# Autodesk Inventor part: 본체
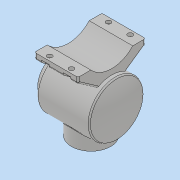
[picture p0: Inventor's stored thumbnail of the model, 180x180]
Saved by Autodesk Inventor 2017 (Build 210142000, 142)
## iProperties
Part Number: 본체
Material: 일반
Document SubType Name: Modeling
Designer: MRC
Density: 1 g/cm^3
Appearance: 기본값
Author: MRC
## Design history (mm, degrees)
sketch "스케치1"
  geometry: L1 (-62, 0)-(58, 0); L2 (41.887, 43)-(-43, 43); L3 (-43, 43)-(-43, 27); L4 (-43, 27)-(-62, 27); L5 (-62, 27)-(-62, 36); L6 (-62, 36)-(-50, 36); L7 (-50, 36)-(-50, 50); L8 (-50, 50)-(46.336, 50); A1 r 106 centre (-55, 0) between (51, 0) and (41.887, 43); A2 r 113 centre (-55, 0) between (58, 0) and (46.336, 50); 1 further point
  constraints: 16 end point, 4 perpendicular, 4 point on circle, 3 horizontal, 3 point on line, 2 centre point, 1 coincident, 1 vertical, 1 vertical alignment
  dimensions: "d6" = 120 distance of L1.end L1.start; "d7" = 62 distance of point (0, 0) L1.start; "d8" = 72 diameter of L6 L1; "d9" = 54 diameter of L4 L1; "d10" = 100 diameter of L8 L1; "d11" = 86 diameter of L2 L1; "d12" = 113 radius of A2; "d14" = 7 radial gap between concentric circles of A2 A1; "d24" = 19 distance of L3.end L4.end; "d25" = 108 distance from line of L7 L1.end
revolve "회전1" sketch "스케치1" stored, may be unused: angle "d15" = 90 deg
node "작업 평면1"
sketch "스케치2"
  geometry: C1 r 36 at (0, 0); 1 further point
  constraints: 1 centre point, 1 coincident
  dimensions: "d17" = 72 diameter of C1
extrude "돌출1" join sketch "스케치2" stored distance "d18" = 10; taper "d19" = 0 deg
node "작업 평면2"
sketch "스케치3"
  geometry: L1 (26.694, 42.278)-(62, 67); L2 (62, 67)-(62, 77); L3 (62, 77)-(38.5, 77); L4 (-26.694, 42.278)-(-62, 67); L5 (-62, 67)-(-62, 77); L6 (-62, 77)-(-38.5, 77); A1 r 50 centre (0, 0) between (26.694, 42.278) and (-26.694, 42.278) reference; A2 r 52.096 centre (0, 112.096) between (-38.5, 77) and (38.5, 77); 1 further point
  constraints: 12 end point, 4 point on circle, 2 equal length, 2 vertical, 1 centre point, 1 collinear, 1 horizontal, 1 perpendicular, 1 vertical alignment
  dimensions: "d26" = 77 distance of L6.end L3.end; "d27" = 77 distance from line of L6 point (0, 0); "d28" = 124 distance between parallel lines of L5 L2; "d29" = 17 distance edge to line of A2 L6; "d30" = 10 distance of L4.end L5.end; "d31" = 55 deg angle of L4 L5; "d32" = 55 deg angle of L1 L2
extrude "돌출2" join sketch "스케치3" distance "d33" = 80; taper "d34" = 0 deg
sketch "스케치4"
  geometry: L1 (0, 0)-(0, 23.5) reference; C1 r 4.5 at (20, 8); 1 further point
  constraints: 1 centre point
  dimensions: "d35" = 54 vertical distance of point (42, 62) C1.centre; "d37" = 9 diameter of C1; "d92" = 20 distance from line of L1 C1.centre
extrude "돌출3" cut sketch "스케치4" distance "d38" = 6; taper "d39" = 0 deg
sketch "스케치5"
  geometry: L1 (7, 0)-(7, -8); L2 (-20, -8)-(60, -8) reference; L3 (-7, 0)-(-7, -8); A1 r 7 centre (0, 0) between (7, 0) and (-7, 0); 1 further point
  constraints: 4 end point, 2 point on circle, 2 point on line, 1 centre point, 1 parallel, 1 perpendicular, 1 tangent
  dimensions: "d46" = 14 diameter of A1
extrude "돌출4" cut sketch "스케치5" stored distance "d47" = 6; taper "d48" = 0 deg
sketch "스케치6"
  geometry: C1 r 27 at (0, 0); 1 further point
  constraints: 1 centre point, 1 coincident
  dimensions: "d52" = 54 diameter of C1
extrude "돌출5" cut sketch "스케치6" stored distance "d53" = 6; taper "d54" = 0 deg
sketch "스케치7"
  geometry: 2 further points
  dimensions: "d55" = 32.5 distance of point (0, 0) point (-32.5, 0)
hole "구멍1" sketch "스케치7" at (-32.5, 0) diameter "d56" = 3.242; stored, may be unused: countersink angle "d60" = 90 deg, drill point angle "d62" = 118 deg; dims "d57" = 8, "d58" = 4, "d59" = 2, "d61" = 10
sketch "스케치8"
  geometry: 2 further points
  dimensions: "d66" = 32.5 distance of point (0, 0) point (-32.5, 0)
hole "구멍2" sketch "스케치8" at (-32.5, 0) diameter "d67" = 3.242; stored, may be unused: countersink angle "d71" = 90 deg, drill point angle "d73" = 118 deg; dims "d68" = 8, "d69" = 4, "d70" = 2, "d72" = 10
sketch "스케치9"
  geometry: 1 further point
fillet "모깎기1" dims "d81" = 3
fillet "모깎기2" dims "d82" = 3
fillet "모깎기3" dims "d83" = 3
fillet "모깎기4" dims "d84" = 3
chamfer "모따기1" distance "d85" = 1; stored, may be unused: second distance "d86" = 2, angle "d87" = 45 deg
node "작업 평면7"
sketch "스케치10"
  geometry: L1 (62, 36)-(62, -36) reference; 2 further points
  constraints: 1 coincident, 1 other
  dimensions: "d89" = 62 distance from line of L1 point (0, 0)
feature "엠보싱1" sketch "스케치10" dims "d6" = 120, "d7" = 62, "d8" = 72, "d9" = 54, "d10" = 100, "d11" = 86, "d12" = 113, "d14" = 7, "d24" = 19, "d25" = 108, "d90" = 0.5, "d91" = 0
node "솔리드1"
pattern_linear "직사각형 패턴1" dims "d42" = 108, "d45" = 40
pattern_linear "직사각형 패턴2" dims "d51" = 40
mirror "미러1"
pattern_circular "원형 패턴1" dims angle "d64" = 360 deg
pattern_circular "원형 패턴2" dims angle "d75" = 360 deg
other parameters: "d16" = -65, "d20" = -42
